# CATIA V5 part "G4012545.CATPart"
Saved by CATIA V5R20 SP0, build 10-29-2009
Part number: G4012545
Revision: 5
Definition: design
Nomenclature: G4012545
Source: made
Description: NOT SPECIFIED
Bounding box of the stored display mesh (mm): x 0 to 45, y -17.817 to 17.817, z -18 to 18
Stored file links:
  C:\Users\Raffaele\Desktop\3D X SITO CF\BOLEX\25-BUSH REF 401\G4012545.CATPart
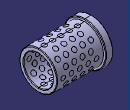
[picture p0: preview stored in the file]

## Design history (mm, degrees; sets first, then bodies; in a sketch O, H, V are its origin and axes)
Body1 "MANIFOLD_SOLID_BREP #10329" (main body)
  Solid1: solid without history
Body2 "MANIFOLD_SOLID_BREP #10480"
  Solid2: solid without history
Body3 "MANIFOLD_SOLID_BREP #10631"
  Solid3: solid without history
Body4 "MANIFOLD_SOLID_BREP #10782"
  Solid4: solid without history
Body5 "MANIFOLD_SOLID_BREP #10933"
  Solid5: solid without history
Body6 "MANIFOLD_SOLID_BREP #11082"
  Solid6: solid without history
Body7 "MANIFOLD_SOLID_BREP #11231"
  Solid7: solid without history
Body8 "MANIFOLD_SOLID_BREP #11380"
  Solid8: solid without history
Body9 "MANIFOLD_SOLID_BREP #11529"
  Solid9: solid without history
Body10 "MANIFOLD_SOLID_BREP #11678"
  Solid10: solid without history
Body11 "MANIFOLD_SOLID_BREP #11827"
  Solid11: solid without history
Body12 "MANIFOLD_SOLID_BREP #11976"
  Solid12: solid without history
Body13 "MANIFOLD_SOLID_BREP #12125"
  Solid13: solid without history
Body14 "MANIFOLD_SOLID_BREP #12274"
  Solid14: solid without history
Body15 "MANIFOLD_SOLID_BREP #12423"
  Solid15: solid without history
Body16 "MANIFOLD_SOLID_BREP #12572"
  Solid16: solid without history
Body17 "MANIFOLD_SOLID_BREP #12721"
  Solid17: solid without history
Body18 "MANIFOLD_SOLID_BREP #12870"
  Solid18: solid without history
Body19 "MANIFOLD_SOLID_BREP #13019"
  Solid19: solid without history
Body20 "MANIFOLD_SOLID_BREP #13168"
  Solid20: solid without history
Body21 "MANIFOLD_SOLID_BREP #13317"
  Solid21: solid without history
Body22 "MANIFOLD_SOLID_BREP #13466"
  Solid22: solid without history
Body23 "MANIFOLD_SOLID_BREP #13615"
  Solid23: solid without history
Body24 "MANIFOLD_SOLID_BREP #13764"
  Solid24: solid without history
Body25 "MANIFOLD_SOLID_BREP #13913"
  Solid25: solid without history
Body26 "MANIFOLD_SOLID_BREP #14062"
  Solid26: solid without history
Body27 "MANIFOLD_SOLID_BREP #14211"
  Solid27: solid without history
Body28 "MANIFOLD_SOLID_BREP #14360"
  Solid28: solid without history
Body29 "MANIFOLD_SOLID_BREP #14509"
  Solid29: solid without history
Body30 "MANIFOLD_SOLID_BREP #14658"
  Solid30: solid without history
Body31 "MANIFOLD_SOLID_BREP #14807"
  Solid31: solid without history
Body32 "MANIFOLD_SOLID_BREP #14958"
  Solid32: solid without history
Body33 "MANIFOLD_SOLID_BREP #15109"
  Solid33: solid without history
Body34 "MANIFOLD_SOLID_BREP #15258"
  Solid34: solid without history
Body35 "MANIFOLD_SOLID_BREP #15407"
  Solid35: solid without history
Body36 "MANIFOLD_SOLID_BREP #15556"
  Solid36: solid without history
Body37 "MANIFOLD_SOLID_BREP #15705"
  Solid37: solid without history
Body38 "MANIFOLD_SOLID_BREP #15854"
  Solid38: solid without history
Body39 "MANIFOLD_SOLID_BREP #16003"
  Solid39: solid without history
Body40 "MANIFOLD_SOLID_BREP #16152"
  Solid40: solid without history
Body41 "MANIFOLD_SOLID_BREP #16301"
  Solid41: solid without history
Body42 "MANIFOLD_SOLID_BREP #16450"
  Solid42: solid without history
Body43 "MANIFOLD_SOLID_BREP #16599"
  Solid43: solid without history
Body44 "MANIFOLD_SOLID_BREP #16748"
  Solid44: solid without history
Body45 "MANIFOLD_SOLID_BREP #16897"
  Solid45: solid without history
Body46 "MANIFOLD_SOLID_BREP #17046"
  Solid46: solid without history
Body47 "MANIFOLD_SOLID_BREP #17195"
  Solid47: solid without history
Body48 "MANIFOLD_SOLID_BREP #17346"
  Solid48: solid without history
Body49 "MANIFOLD_SOLID_BREP #17497"
  Solid49: solid without history
Body50 "MANIFOLD_SOLID_BREP #17646"
  Solid50: solid without history
Body51 "MANIFOLD_SOLID_BREP #17795"
  Solid51: solid without history
Body52 "MANIFOLD_SOLID_BREP #17944"
  Solid52: solid without history
Body53 "MANIFOLD_SOLID_BREP #18093"
  Solid53: solid without history
Body54 "MANIFOLD_SOLID_BREP #18242"
  Solid54: solid without history
Body55 "MANIFOLD_SOLID_BREP #18391"
  Solid55: solid without history
Body56 "MANIFOLD_SOLID_BREP #18540"
  Solid56: solid without history
Body57 "MANIFOLD_SOLID_BREP #18689"
  Solid57: solid without history
Body58 "MANIFOLD_SOLID_BREP #18838"
  Solid58: solid without history
Body59 "MANIFOLD_SOLID_BREP #18987"
  Solid59: solid without history
Body60 "MANIFOLD_SOLID_BREP #19136"
  Solid60: solid without history
Body61 "MANIFOLD_SOLID_BREP #19285"
  Solid61: solid without history
Body62 "MANIFOLD_SOLID_BREP #19434"
  Solid62: solid without history
Body63 "MANIFOLD_SOLID_BREP #19583"
  Solid63: solid without history
Body64 "MANIFOLD_SOLID_BREP #19734"
  Solid64: solid without history
Body65 "MANIFOLD_SOLID_BREP #19885"
  Solid65: solid without history
Body66 "MANIFOLD_SOLID_BREP #20034"
  Solid66: solid without history
Body67 "MANIFOLD_SOLID_BREP #20183"
  Solid67: solid without history
Body68 "MANIFOLD_SOLID_BREP #20332"
  Solid68: solid without history
Body69 "MANIFOLD_SOLID_BREP #20481"
  Solid69: solid without history
Body70 "MANIFOLD_SOLID_BREP #20630"
  Solid70: solid without history
Body71 "MANIFOLD_SOLID_BREP #20779"
  Solid71: solid without history
Body72 "MANIFOLD_SOLID_BREP #20928"
  Solid72: solid without history
Body73 "MANIFOLD_SOLID_BREP #21077"
  Solid73: solid without history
